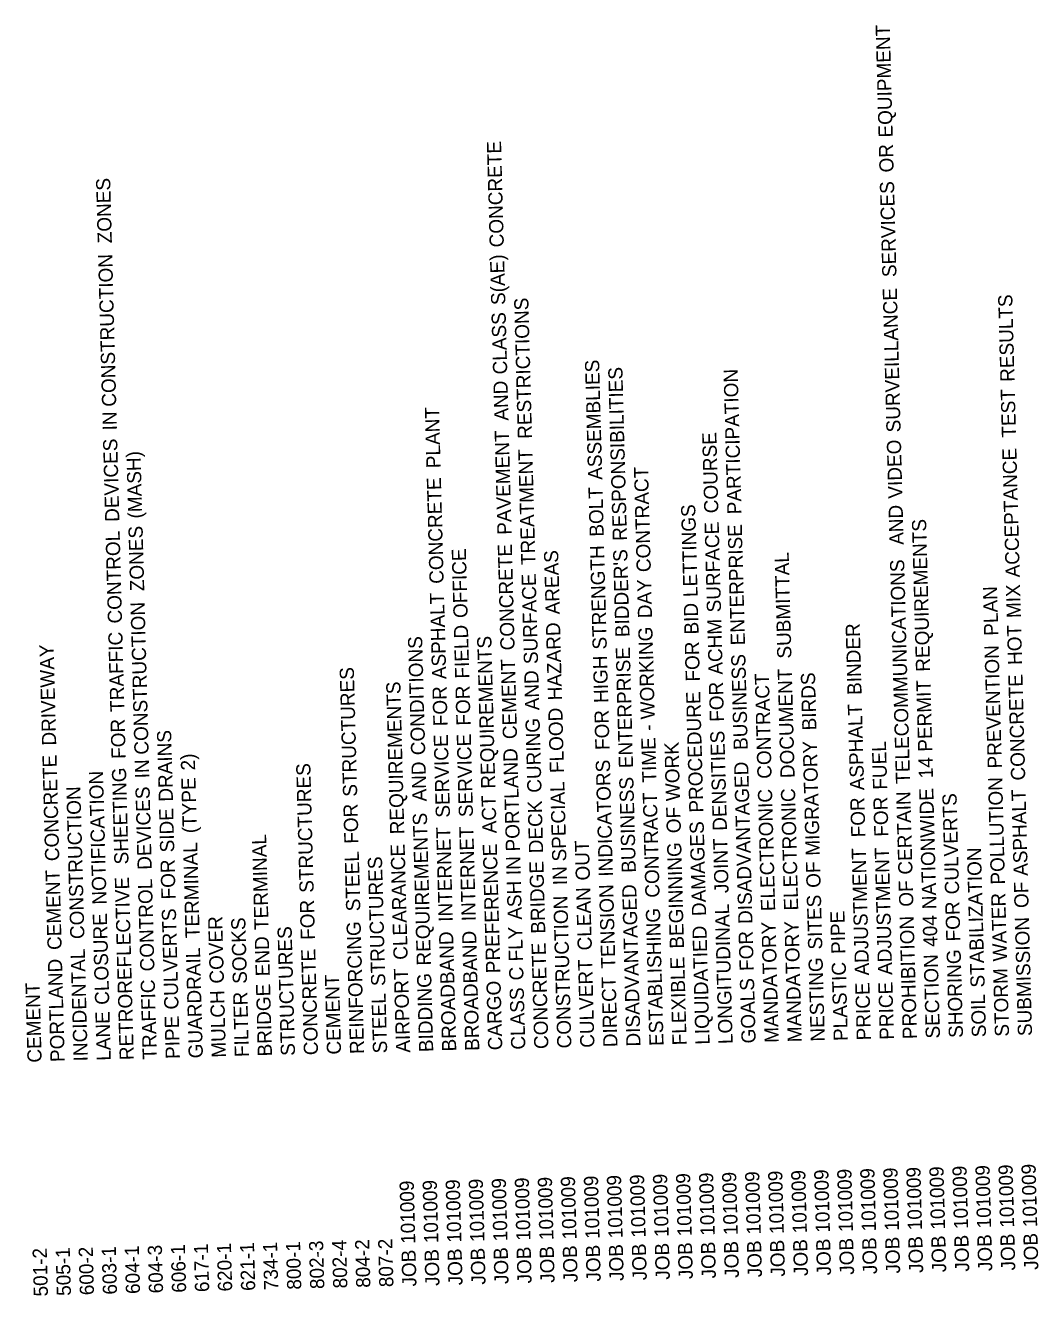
# Model space of a CAD drawing. Extents: x 1929542 to 1931706, y 595440 to 597808.
# Drawn here: x 1929921 to 1930349, y 596400 to 596938 of the extents above; entities that cross this region are included whole.
import ezdxf

# ---------------------------------------------------------------- set-up
doc = ezdxf.new("R2010")
doc.units = 0
doc.layers.add('Default', color=7, linetype='Continuous')

msp = doc.modelspace()

# ---------------------------------------------------------------- texts
at = {"layer": 'Default'}
for s, p in [(' EQUIPMENT', (1930287.64, 596887.98)), (' CONCRETE', (1930123.08, 596841.5)), (' OR', (1930288.04, 596873.2)), (' ZONES', (1929957.22, 596843.23)), (' SERVICES', (1930289.23, 596828.92)), (' CONSTRUCTION', (1929959.08, 596774.08)), (' S(AE)', (1930123.73, 596817.12)), (' RESTRICTIONS', (1930135.01, 596760.5)), (' SURVEILLANCE', (1930290.99, 596763.23)), (' RESULTS', (1930339.18, 596784.61)), (' CLASS', (1930124.52, 596787.75)), (' ASSEMBLIES', (1930164.73, 596743.15)), (' RESPONSIBILITIES', (1930175.18, 596717.35)), (' PARTICIPATION', (1930223.65, 596728.58)), (' AND', (1930125.05, 596768.17)), (' TEST', (1930339.82, 596761.03)), (' IN', (1929959.35, 596764.06)), (' PLANT', (1930096.33, 596748.07)), (' PAVEMENT', (1930126.34, 596719.91)), (' COURSE', (1930213.88, 596729)), (' DEVICES', (1929960.39, 596725.37)), (' TREATMENT', (1930136.44, 596707.12)), (' VIDEO', (1930291.74, 596735.2)), (' ACCEPTANCE', (1930341.41, 596701.86)), (' (MASH)', (1929970.1, 596726.79)), (' CONTRACT', (1930185.29, 596704.1)), (' CONCRETE', (1930097.64, 596699.16)), (' BOLT', (1930165.38, 596719.1)), (' LETTINGS', (1930205.08, 596693.56)), (' AND', (1930292.27, 596715.62)), (' ZONES', (1929970.93, 596696.03)), (' SURFACE', (1930215.01, 596687.07)), (' ENTERPRISE', (1930225.13, 596673.14)), (' REQUIREMENTS', (1930303.46, 596661.96)), (' CONTROL', (1929961.54, 596682.37)), (' OFFICE', (1930107.78, 596684.7)), (' CONCRETE', (1930127.66, 596671)), (' AREAS', (1930146.76, 596686.19)), (' STRENGTH', (1930166.66, 596671.35)), (" BIDDER'S", (1930176.27, 596676.6)), (' SUBMITTAL', (1930244.79, 596667.52)), (' TELECOMMUNICATIONS', (1930294.98, 596614.56)), (' SURFACE', (1930137.57, 596665.19)), (' DAY', (1930185.81, 596684.6)), (' PLAN', (1930332.32, 596677.18)), (' MIX', (1930341.87, 596684.69)), (' CONSTRUCTION', (1929972.79, 596626.88)), (' ASPHALT', (1930098.72, 596658.81)), (' BID', (1930205.51, 596677.71)), (' FIELD', (1930108.47, 596659.07)), (' HAZARD', (1930147.73, 596649.86)), (' WORKING', (1930186.96, 596641.83)), (' ACHM', (1930215.72, 596660.7)), (' BINDER', (1930274.47, 596652.16)), (' HOT', (1930342.4, 596664.84)), (' TRAFFIC', (1929962.55, 596644.99)), (' CONDITIONS', (1930089.83, 596626.64)), (' REQUIREMENTS', (1930119.47, 596612.49)), (' DRIVEWAY', (1929933.67, 596630.72)), (' ENTERPRISE', (1930177.76, 596621.16)), (' FOR', (1930206.04, 596657.81)), (' PREVENTION', (1930333.82, 596621.05)), (' CEMENT', (1930128.67, 596633.45)), (' HIGH', (1930167.27, 596648.75)), (' BUSINESS', (1930226.32, 596628.87)), (' STRUCTURES', (1930061.04, 596609.1)), (' AND', (1930138.09, 596645.62)), (' CONTRACT', (1930236.4, 596616.68)), (' DOCUMENT', (1930246.15, 596616.94)), (' BIRDS', (1930255.36, 596637.14)), (' CONCRETE', (1930343.71, 596615.93)), (' REQUIREMENTS', (1930080.98, 596593.19)), (' FOR', (1930099.26, 596638.91)), (' FOR', (1930109, 596639.17)), (' PROCEDURE', (1930207.53, 596602.37)), (' FOR', (1930216.25, 596640.79)), (' PERMIT', (1930304.37, 596628.13)), (' ASPHALT', (1930275.55, 596611.8)), (' FLOOD', (1930148.56, 596619.11)), (' FOR', (1930167.8, 596628.85)), (' FOR', (1929963.08, 596625.09)), (' DRAINS', (1929983.07, 596606.98)), (' CURING', (1930139.03, 596610.76)), (' -', (1930187.09, 596636.98)), (' SERVICE', (1930100.3, 596600.23)), (' SERVICE', (1930110.04, 596600.49)), (' TIME', (1930187.68, 596615.08)), (' WORK', (1930197.64, 596607.23)), (' DENSITIES', (1930217.49, 596594.66)), (' MIGRATORY', (1930256.79, 596584.12)), (' FUEL', (1930285.3, 596612.06)), (' CONCRETE', (1929934.98, 596581.81)), (' 2)', (1929992.47, 596620.21)), (' PORTLAND', (1930129.94, 596585.93)), (' SHEETING', (1929964.28, 596580.44)), (' IN', (1929973.05, 596616.86)), (' STRUCTURES', (1930042.63, 596568.44)), (' AND', (1930090.36, 596607.06)), (' INDICATORS', (1930169.24, 596575.27)), (' DISADVANTAGED', (1930228.3, 596555.27)), (' 14', (1930304.67, 596616.9)), (' NOTIFICATION', (1929954.98, 596563.44)), (' (TYPE', (1929993.18, 596593.65)), (' BUSINESS', (1930178.95, 596576.89)), (' POLLUTION', (1930335.14, 596571.91)), (' CONSTRUCTION', (1929945.62, 596548.86)), (' DEVICES', (1929974.09, 596578.17)), (' SPECIAL', (1930149.56, 596581.68)), (' CONTRACT', (1930188.99, 596566.36)), (' ELECTRONIC', (1930237.91, 596560.67)), (' ELECTRONIC', (1930247.65, 596560.93)), (' CERTAIN', (1930296.01, 596576.13)), (' NATIONWIDE', (1930306.16, 596561.48)), (' CULVERTS', (1930315.75, 596567.77)), (' ASPHALT', (1930344.8, 596575.58)), (' FOR', (1930061.58, 596589.2)), (' ACT', (1930119.98, 596593.57)), (' DECK', (1930139.72, 596585.16)), (' FOR', (1930276.08, 596591.9)), (' FOR', (1930285.83, 596592.16)), (' SIDE', (1929983.65, 596585.53)), (' REQUIREMENTS', (1930092.22, 596537.65)), (' OF', (1930198.01, 596593.65)), (' INTERNET', (1930101.48, 596556.17)), (' INTERNET', (1930111.23, 596556.43)), (' DAMAGES', (1930208.7, 596558.57)), (' TERMINAL', (1929994.38, 596549.24)), (' TERMINAL', (1930023.54, 596552.69)), (' CLEARANCE', (1930082.4, 596540.08)), (' PREFERENCE', (1930121.57, 596534.4)), (' OUT', (1930159.53, 596573.63)), (' BEGINNING', (1930199.32, 596544.82)), (' JOINT', (1930218.2, 596568.29)), (' STEEL', (1930062.35, 596560.61)), (' STRUCTURES', (1930072.95, 596528.99)), (' IN', (1930130.21, 596575.91)), (' ADJUSTMENT', (1930277.65, 596533.4)), (' ADJUSTMENT', (1930287.4, 596533.66)), (' STABILIZATION', (1930326.56, 596528.34)), (' CEMENT', (1929935.99, 596544.26)), (' FOR', (1929984.18, 596565.63)), (' BRIDGE', (1930140.63, 596551.15)), (' IN', (1930149.83, 596571.66)), (' OF', (1930257.15, 596570.54)), ('RETROREFLECTIVE', (1929966.44, 596499.86)), (' CONTROL', (1929975.25, 596535.17)), (' ASH', (1930130.72, 596557.03)), (' OF', (1930296.38, 596562.55)), (' OF', (1930345.16, 596562)), (' CLEAN', (1930160.33, 596544.04)), (' TENSION', (1930170.29, 596536.38)), ('DISADVANTAGED', (1930180.86, 596505.61)), (' SITES', (1930257.85, 596544.43)), (' WATER', (1930336.01, 596539.43)), (' FOR', (1930043.16, 596548.53)), ('CONSTRUCTION', (1930151.63, 596504.83)), ('LONGITUDINAL', (1930219.85, 596506.66)), (' FOR', (1930316.28, 596547.86)), (' CLOSURE', (1929956.12, 596521.04)), (' CULVERTS', (1929985.43, 596519.03)), (' COVER', (1930004.65, 596530.02)), (' SOCKS', (1930014.4, 596529.92)), ('ESTABLISHING', (1930190.61, 596505.88)), (' PIPE', (1930267.65, 596542.57)), ('PROHIBITION', (1930297.82, 596508.75)), (' 404', (1930306.59, 596545.58)), ('SUBMISSION', (1930346.55, 596510.06)), ('STRUCTURES', (1930034.67, 596501.69)), ('REINFORCING', (1930063.91, 596502.47)), ('BROADBAND', (1930102.89, 596503.52)), ('BROADBAND', (1930112.64, 596503.78)), (' FLY', (1930131.19, 596539.4)), ('LIQUIDATIED', (1930210.1, 596506.4)), (' FOR', (1930228.83, 596535.36)), ('MANDATORY', (1930239.34, 596507.18)), ('MANDATORY', (1930249.09, 596507.44)), (' END', (1930024.07, 596533.11)), ('CONCRETE', (1930141.88, 596504.57)), ('INCIDENTAL', (1929946.95, 596499.33)), ('GUARDRAIL', (1929995.68, 596500.64)), ('CONCRETE', (1930044.41, 596501.95)), ('FLEXIBLE', (1930200.36, 596506.14)), ('NESTING', (1930258.84, 596507.71)), ('SECTION', (1930307.57, 596509.01)), ('SHORING', (1930317.32, 596509.28)), ('PORTLAND', (1929937.2, 596499.07)), ('AIRPORT', (1930083.4, 596503)), (' C', (1930131.41, 596531.35)), ('CULVERT', (1930161.37, 596505.09)), ('PLASTIC', (1930268.58, 596507.97)), ('STORM', (1930336.81, 596509.8)), ('CEMENT', (1929927.46, 596498.81)), ('TRAFFIC', (1929976.19, 596500.12)), ('BRIDGE', (1930024.92, 596501.43)), ('CEMENT', (1930054.16, 596502.21)), ('BIDDING', (1930093.15, 596503.26)), ('CARGO', (1930122.39, 596504.04)), ('DIRECT', (1930171.12, 596505.35)), ('GOALS', (1930229.6, 596506.92)), ('PRICE', (1930278.33, 596508.23)), ('PRICE', (1930288.08, 596508.49)), ('MULCH', (1930005.43, 596500.9)), ('FILTER', (1930015.17, 596501.17)), ('STEEL', (1930073.65, 596502.74)), ('CLASS', (1930132.13, 596504.31)), ('SOIL', (1930327.06, 596509.54)), ('LANE', (1929956.7, 596499.6)), ('PIPE', (1929985.93, 596500.38)), (' 101009', (1930183.09, 596422.54)), (' 101009', (1930192.84, 596422.8)), (' 101009', (1930202.59, 596423.06)), (' 101009', (1930212.33, 596423.33)), (' 101009', (1930222.08, 596423.59)), (' 101009', (1930231.83, 596423.85)), (' 101009', (1930241.57, 596424.11)), (' 101009', (1930251.32, 596424.37)), (' 101009', (1930261.07, 596424.63)), (' 101009', (1930270.81, 596424.9)), (' 101009', (1930280.56, 596425.16)), (' 101009', (1930290.31, 596425.42)), (' 101009', (1930300.05, 596425.68)), (' 101009', (1930309.8, 596425.94)), (' 101009', (1930319.55, 596426.2)), (' 101009', (1930329.29, 596426.47)), (' 101009', (1930339.04, 596426.73)), (' 101009', (1930348.78, 596426.99)), (' 101009', (1930085.63, 596419.92)), (' 101009', (1930095.38, 596420.19)), (' 101009', (1930105.12, 596420.45)), (' 101009', (1930114.87, 596420.71)), (' 101009', (1930124.62, 596420.97)), (' 101009', (1930134.36, 596421.23)), (' 101009', (1930144.11, 596421.49)), (' 101009', (1930153.86, 596421.76)), (' 101009', (1930163.6, 596422.02)), (' 101009', (1930173.35, 596422.28)), ('JOB', (1930271.24, 596409.04)), ('JOB', (1930280.98, 596409.3)), ('JOB', (1930290.73, 596409.56)), ('JOB', (1930300.48, 596409.83)), ('JOB', (1930310.22, 596410.09)), ('JOB', (1930319.97, 596410.35)), ('JOB', (1930329.72, 596410.61)), ('JOB', (1930339.46, 596410.87)), ('JOB', (1930349.21, 596411.13)), ('501-2', (1929930.11, 596399.88)), ('505-1', (1929939.86, 596400.15)), ('600-2', (1929949.6, 596400.41)), ('603-1', (1929959.35, 596400.67)), ('604-1', (1929969.1, 596400.93)), ('604-3', (1929978.84, 596401.19)), ('606-1', (1929988.59, 596401.45)), ('617-1', (1929998.34, 596401.72)), ('620-1', (1930008.08, 596401.98)), ('621-1', (1930017.83, 596402.24)), ('734-1', (1930027.58, 596402.5)), ('800-1', (1930037.32, 596402.76)), ('802-3', (1930047.07, 596403.02)), ('802-4', (1930056.82, 596403.29)), ('804-2', (1930066.56, 596403.55)), ('807-2', (1930076.31, 596403.81)), ('JOB', (1930086.06, 596404.07)), ('JOB', (1930095.8, 596404.33)), ('JOB', (1930105.55, 596404.59)), ('JOB', (1930115.29, 596404.86)), ('JOB', (1930125.04, 596405.12)), ('JOB', (1930134.79, 596405.38)), ('JOB', (1930144.53, 596405.64)), ('JOB', (1930154.28, 596405.9)), ('JOB', (1930164.03, 596406.16)), ('JOB', (1930173.77, 596406.43)), ('JOB', (1930183.52, 596406.69)), ('JOB', (1930193.27, 596406.95)), ('JOB', (1930203.01, 596407.21)), ('JOB', (1930212.76, 596407.47)), ('JOB', (1930222.51, 596407.73)), ('JOB', (1930232.25, 596407.99)), ('JOB', (1930242, 596408.26)), ('JOB', (1930251.75, 596408.52)), ('JOB', (1930261.49, 596408.78))]:
    msp.add_text(s, height=6, rotation=91.5377, dxfattribs=at).set_placement(p)

doc.saveas('drawing.dxf')
